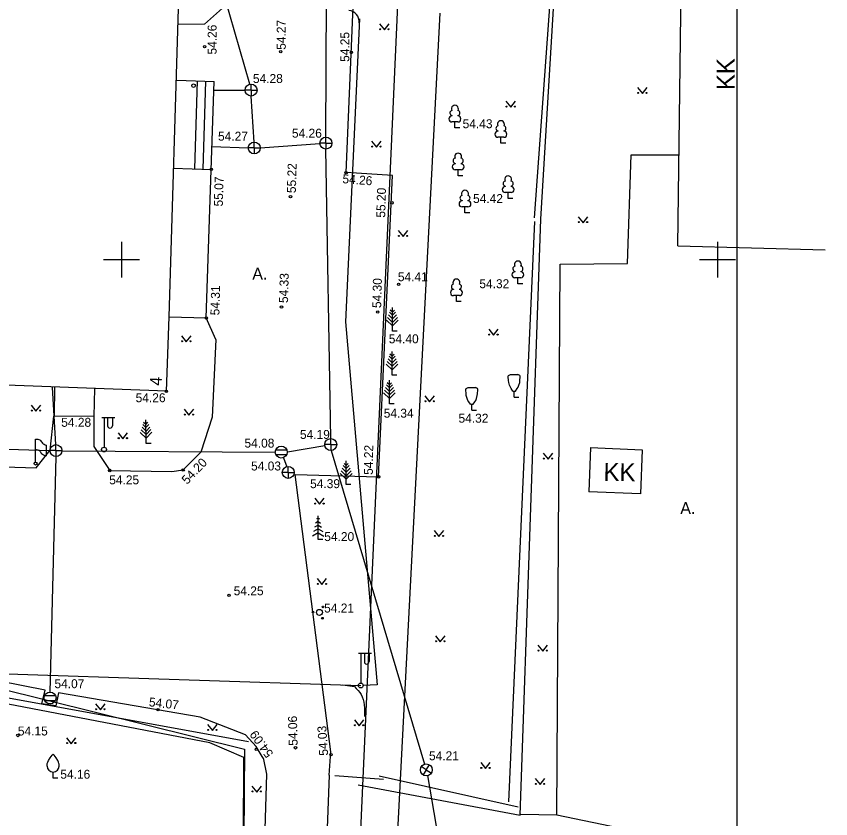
# Model space of a CAD drawing. Extents: x 9156 to 9809, y 2728 to 4000.
# Drawn here: x 9741.2 to 9809.5, y 3703.1 to 3770.4 of the extents above; entities that cross this region are included whole.
import ezdxf

# ---------------------------------------------------------------- set-up
doc = ezdxf.new("R2010")
doc.units = 0
for name, color, linetype in [('Level 1', 7, 'Continuous'), ('Level 54', 7, 'Continuous'), ('Level 63', 7, 'Continuous')]:
    doc.layers.add(name, color=color, linetype=linetype)

msp = doc.modelspace()

# ---------------------------------------------------------------- linework, layer by layer
at = {"layer": 'Level 1'}
for p, q in [((9518.632, 3768.823), (9760.318, 3708.94)), ((9518.632, 3768.823), (9760.318, 3708.94)), ((9760.318, 3708.94), (9759.918, 3646.584)), ((9760.318, 3708.94), (9759.918, 3646.584))]:
    msp.add_line(p, q, dxfattribs=at)
at = {"layer": 'Level 54'}
for p, q in [((9785.171, 3753.397), (9789.782, 3829.186)), ((9774.628, 3803.86), (9769.636, 3693.047)), ((9784.66, 3753.508), (9788.046, 3800.39)), ((9753.989, 3745.191), (9755.299, 3788.499)), ((9767.154, 3760.265), (9767.24, 3788.334)), ((9760.753, 3764.715), (9757.639, 3775.604)), ((9772.838, 3695.211), (9776.735, 3770.688)), ((9756.967, 3769.743), (9754.736, 3769.733)), ((9769.959, 3770.201), (9768.796, 3744.791)), ((9771.656, 3769.774), (9772.059, 3769.269)), ((9772.059, 3769.269), (9772.456, 3769.774)), ((9754.631, 3765.053), (9757.774, 3764.948)), ((9756.164, 3757.619), (9756.387, 3764.995)), ((9756.857, 3757.595), (9757.08, 3764.972)), ((9760.371, 3764.183), (9757.748, 3764.199)), ((9760.868, 3764.22), (9760.368, 3764.22)), ((9760.868, 3764.22), (9760.868, 3764.72)), ((9760.868, 3764.22), (9761.368, 3764.22)), ((9760.868, 3764.22), (9760.868, 3763.72)), ((9793.302, 3764.435), (9793.705, 3763.93)), ((9793.705, 3763.93), (9794.102, 3764.435)), ((9761.13, 3759.861), (9760.88, 3763.715)), ((9782.256, 3763.287), (9782.659, 3762.781)), ((9782.659, 3762.781), (9783.056, 3763.287)), ((9777.721, 3762.085), (9777.721, 3762.053)), ((9778.221, 3761.553), (9777.721, 3761.553)), ((9777.971, 3761.053), (9777.971, 3761.553)), ((9778.221, 3762.085), (9778.221, 3762.053)), ((9778.371, 3761.053), (9777.971, 3761.053)), ((9781.581, 3760.794), (9781.581, 3760.762)), ((9782.081, 3760.794), (9782.081, 3760.762)), ((9767.15, 3759.771), (9767.15, 3760.271)), ((9782.081, 3760.262), (9781.581, 3760.262)), ((9781.831, 3759.762), (9781.831, 3760.262)), ((9760.636, 3759.354), (9757.59, 3759.459)), ((9761.139, 3759.365), (9761.139, 3759.865)), ((9761.646, 3759.366), (9766.639, 3759.749)), ((9767.15, 3759.771), (9766.65, 3759.771)), ((9767.15, 3759.771), (9767.65, 3759.771)), ((9767.15, 3759.771), (9767.15, 3759.271)), ((9770.986, 3759.931), (9771.389, 3759.426)), ((9771.389, 3759.426), (9771.786, 3759.931)), ((9782.231, 3759.762), (9781.831, 3759.762)), ((9761.139, 3759.365), (9760.639, 3759.365)), ((9761.139, 3759.365), (9761.639, 3759.365)), ((9761.139, 3759.365), (9761.139, 3758.865)), ((9767.568, 3734.982), (9767.144, 3759.264)), ((9777.992, 3758.07), (9777.992, 3758.038)), ((9778.492, 3758.07), (9778.492, 3758.038)), ((9754.34, 3757.68), (9757.527, 3757.573)), ((9778.492, 3757.538), (9777.992, 3757.538)), ((9778.242, 3757.038), (9778.242, 3757.538)), ((9778.642, 3757.038), (9778.242, 3757.038)), ((9782.187, 3756.158), (9782.187, 3756.126)), ((9782.687, 3756.158), (9782.687, 3756.126)), ((9782.687, 3755.626), (9782.187, 3755.626)), ((9782.437, 3755.126), (9782.437, 3755.626)), ((9778.566, 3754.955), (9778.566, 3754.923)), ((9779.066, 3754.955), (9779.066, 3754.923)), ((9782.837, 3755.126), (9782.437, 3755.126)), ((9779.066, 3754.423), (9778.566, 3754.423)), ((9778.816, 3753.923), (9778.816, 3754.423)), ((9779.216, 3753.923), (9778.816, 3753.923)), ((9783.44, 3703.4), (9785.171, 3753.397)), ((9788.314, 3753.603), (9788.717, 3753.098)), ((9788.717, 3753.098), (9789.114, 3753.603)), ((9784.647, 3753.209), (9782.461, 3704.513)), ((9773.218, 3752.437), (9773.621, 3751.932)), ((9773.621, 3751.932), (9774.018, 3752.437)), ((9750, 3751.5), (9750, 3748.5)), ((9800, 3751.5), (9800, 3748.5)), ((9796.678, 3751.167), (9809.033, 3750.808)), ((9748.5, 3750), (9751.5, 3750)), ((9798.5, 3750), (9801.5, 3750)), ((9783.006, 3749.013), (9783.006, 3748.981)), ((9783.506, 3748.481), (9783.006, 3748.481)), ((9783.256, 3747.981), (9783.256, 3748.481)), ((9783.506, 3749.013), (9783.506, 3748.981)), ((9783.656, 3747.981), (9783.256, 3747.981)), ((9777.847, 3747.515), (9777.847, 3747.482)), ((9778.347, 3747.515), (9778.347, 3747.482)), ((9778.347, 3746.982), (9777.847, 3746.982)), ((9778.097, 3746.482), (9778.097, 3746.982)), ((9778.497, 3746.482), (9778.097, 3746.482)), ((9772.731, 3745.588), (9772.55, 3745.769)), ((9772.731, 3743.988), (9772.731, 3745.988)), ((9772.731, 3745.588), (9772.912, 3745.769)), ((9757.913, 3743.3), (9757.11, 3745.104)), ((9772.731, 3744.738), (9772.32, 3745.149)), ((9772.731, 3745.038), (9772.401, 3745.368)), ((9772.731, 3745.338), (9772.482, 3745.587)), ((9772.731, 3745.338), (9772.98, 3745.587)), ((9772.731, 3745.038), (9773.061, 3745.368)), ((9772.731, 3744.738), (9773.142, 3745.149)), ((9768.796, 3744.791), (9771.443, 3714.328)), ((9772.731, 3744.438), (9772.239, 3744.93)), ((9772.731, 3744.438), (9773.223, 3744.93)), ((9773.131, 3743.988), (9772.731, 3743.988)), ((9780.805, 3744.16), (9781.208, 3743.654)), ((9781.208, 3743.654), (9781.605, 3744.16)), ((9755.031, 3743.6), (9755.434, 3743.095)), ((9755.434, 3743.095), (9755.831, 3743.6)), ((9772.703, 3740.3), (9772.703, 3742.3)), ((9772.703, 3741.35), (9772.373, 3741.68)), ((9772.703, 3741.65), (9772.454, 3741.899)), ((9772.703, 3741.9), (9772.522, 3742.081)), ((9772.703, 3741.9), (9772.884, 3742.081)), ((9772.703, 3741.65), (9772.951, 3741.899)), ((9772.703, 3741.35), (9773.032, 3741.68)), ((9772.703, 3740.75), (9772.211, 3741.242)), ((9772.703, 3741.05), (9772.292, 3741.461)), ((9772.703, 3741.05), (9773.113, 3741.461)), ((9772.703, 3740.75), (9773.195, 3741.242)), ((9773.103, 3740.3), (9772.703, 3740.3)), ((9782.644, 3740.369), (9783.244, 3740.369)), ((9753.767, 3738.957), (9723.208, 3740.129)), ((9772.478, 3739.494), (9772.297, 3739.675)), ((9772.478, 3737.894), (9772.478, 3739.894)), ((9772.478, 3739.494), (9772.659, 3739.675)), ((9744.503, 3734.483), (9744.199, 3739.278)), ((9744.39, 3739.317), (9744.351, 3736.881)), ((9747.729, 3739.189), (9747.691, 3736.827)), ((9772.478, 3738.644), (9772.067, 3739.054)), ((9772.478, 3738.944), (9772.148, 3739.273)), ((9772.478, 3739.244), (9772.229, 3739.492)), ((9772.478, 3739.244), (9772.726, 3739.492)), ((9772.478, 3738.944), (9772.807, 3739.273)), ((9772.478, 3738.644), (9772.889, 3739.054)), ((9779.09, 3739.263), (9779.69, 3739.263)), ((9782.844, 3738.969), (9783.044, 3738.969)), ((9782.944, 3738.469), (9782.944, 3738.969)), ((9772.478, 3738.344), (9771.986, 3738.836)), ((9772.478, 3738.344), (9772.97, 3738.836)), ((9775.449, 3738.567), (9775.852, 3738.062)), ((9775.852, 3738.062), (9776.249, 3738.567)), ((9782.944, 3738.469), (9783.344, 3738.469)), ((9742.422, 3737.784), (9742.825, 3737.279)), ((9742.825, 3737.279), (9743.222, 3737.784)), ((9772.878, 3737.894), (9772.478, 3737.894)), ((9779.29, 3737.863), (9779.49, 3737.863)), ((9779.39, 3737.363), (9779.39, 3737.863)), ((9747.691, 3736.827), (9744.351, 3736.881)), ((9747.691, 3736.827), (9747.691, 3736.827)), ((9755.254, 3737.448), (9755.657, 3736.943)), ((9755.657, 3736.943), (9756.054, 3737.448)), ((9779.39, 3737.363), (9779.79, 3737.363)), ((9748.335, 3736.764), (9749.435, 3736.763)), ((9748.535, 3736.764), (9748.531, 3734.264)), ((9748.835, 3736.763), (9748.834, 3736.063)), ((9749.235, 3736.763), (9749.234, 3736.063)), ((9752.049, 3735.916), (9751.795, 3736.159)), ((9752.043, 3736.166), (9751.858, 3736.343)), ((9752.08, 3734.567), (9752.034, 3736.566)), ((9752.043, 3736.166), (9752.22, 3736.352)), ((9752.049, 3735.916), (9752.292, 3736.171)), ((9749.712, 3735.472), (9750.115, 3734.967)), ((9750.115, 3734.967), (9750.512, 3735.472)), ((9752.07, 3735.017), (9751.567, 3735.497)), ((9752.063, 3735.317), (9751.643, 3735.718)), ((9752.056, 3735.616), (9751.719, 3735.939)), ((9752.056, 3735.616), (9752.378, 3735.954)), ((9752.063, 3735.317), (9752.464, 3735.737)), ((9752.07, 3735.017), (9752.55, 3735.52)), ((9742.786, 3733.015), (9742.786, 3734.941)), ((9742.786, 3733.015), (9742.786, 3734.941)), ((9767.556, 3734.489), (9767.556, 3734.989)), ((9719.974, 3734.745), (9743.999, 3733.987)), ((9743.687, 3734.437), (9743.687, 3733.547)), ((9743.687, 3734.437), (9743.687, 3733.547)), ((9744.503, 3733.983), (9744.503, 3734.483)), ((9752.48, 3734.576), (9752.08, 3734.567)), ((9763.914, 3733.865), (9767.061, 3734.403)), ((9767.556, 3734.489), (9767.056, 3734.489)), ((9767.556, 3734.489), (9768.056, 3734.489)), ((9767.556, 3734.489), (9767.556, 3733.989)), ((9789.34, 3734.253), (9789.195, 3730.514)), ((9789.34, 3734.253), (9793.692, 3734.034)), ((9744.503, 3733.983), (9744.003, 3733.983)), ((9744.006, 3713.727), (9744.507, 3733.462)), ((9744.503, 3733.983), (9745.003, 3733.983)), ((9744.503, 3733.983), (9744.503, 3733.483)), ((9745.004, 3733.97), (9762.922, 3733.856)), ((9762.944, 3734.055), (9763.86, 3734.055)), ((9762.944, 3733.655), (9763.86, 3733.655)), ((9767.576, 3733.979), (9775.425, 3707.676)), ((9785.38, 3733.757), (9785.783, 3733.252)), ((9785.783, 3733.252), (9786.18, 3733.757)), ((9793.692, 3734.034), (9793.55, 3730.346)), ((9763.583, 3733.384), (9763.857, 3732.621)), ((9768.848, 3732.472), (9768.6, 3732.72)), ((9768.848, 3732.722), (9768.667, 3732.903)), ((9768.848, 3731.122), (9768.848, 3733.122)), ((9768.848, 3732.722), (9769.029, 3732.903)), ((9768.848, 3732.472), (9769.097, 3732.72)), ((9763.99, 3732.147), (9763.49, 3732.147)), ((9763.99, 3732.147), (9763.99, 3732.647)), ((9763.99, 3732.147), (9764.49, 3732.147)), ((9763.99, 3732.147), (9763.99, 3731.647)), ((9768.848, 3731.572), (9768.356, 3732.064)), ((9768.848, 3731.872), (9768.437, 3732.282)), ((9768.848, 3732.172), (9768.518, 3732.501)), ((9768.848, 3732.172), (9769.178, 3732.501)), ((9768.848, 3731.872), (9769.259, 3732.282)), ((9768.848, 3731.572), (9769.34, 3732.064)), ((9769.248, 3731.122), (9768.848, 3731.122)), ((9766.208, 3729.988), (9766.611, 3729.482)), ((9766.611, 3729.482), (9767.008, 3729.988)), ((9793.55, 3730.346), (9789.195, 3730.514)), ((9766.493, 3728.018), (9766.281, 3727.901)), ((9766.493, 3728.318), (9766.367, 3728.248)), ((9766.493, 3726.518), (9766.493, 3728.518)), ((9766.493, 3728.318), (9766.619, 3728.248)), ((9766.493, 3728.018), (9766.705, 3727.901)), ((9766.493, 3727.418), (9766.109, 3727.205)), ((9766.493, 3727.718), (9766.195, 3727.553)), ((9766.493, 3727.718), (9766.791, 3727.553)), ((9766.493, 3727.418), (9766.877, 3727.205)), ((9776.23, 3727.27), (9776.633, 3726.765)), ((9776.633, 3726.765), (9777.03, 3727.27)), ((9766.493, 3727.068), (9766.018, 3726.804)), ((9766.493, 3727.068), (9766.968, 3726.804)), ((9766.893, 3726.518), (9766.493, 3726.518)), ((9766.411, 3723.243), (9766.814, 3722.738)), ((9766.814, 3722.738), (9767.211, 3723.243)), ((9776.342, 3718.433), (9776.745, 3717.928)), ((9776.745, 3717.928), (9777.142, 3718.433)), ((9760.645, 3709.542), (9715.664, 3717.757)), ((9784.933, 3717.65), (9785.336, 3717.145)), ((9785.336, 3717.145), (9785.733, 3717.65)), ((9769.872, 3716.974), (9770.972, 3716.974)), ((9770.072, 3716.974), (9770.072, 3714.474)), ((9770.372, 3716.974), (9770.372, 3716.274)), ((9770.772, 3716.974), (9770.772, 3716.274)), ((9739.367, 3715.288), (9770.072, 3714.274)), ((9768.565, 3714.327), (9769.542, 3714.187)), ((9771.443, 3714.328), (9770.272, 3714.274)), ((9743.548, 3713.427), (9744.464, 3713.427)), ((9743.548, 3713.027), (9744.464, 3713.027)), ((9747.822, 3712.732), (9748.225, 3712.227)), ((9748.225, 3712.227), (9748.622, 3712.732)), ((9757.227, 3711.001), (9757.63, 3710.496)), ((9757.63, 3710.496), (9758.027, 3711.001)), ((9769.536, 3711.387), (9769.939, 3710.881)), ((9769.939, 3710.881), (9770.336, 3711.387)), ((9745.379, 3709.896), (9745.779, 3709.392)), ((9745.779, 3709.392), (9746.179, 3709.896)), ((9775.572, 3707.198), (9775.15, 3707.468)), ((9775.572, 3707.198), (9775.841, 3707.62)), ((9780.136, 3707.807), (9780.539, 3707.302)), ((9780.539, 3707.302), (9780.936, 3707.807)), ((9744.263, 3706.511), (9744.263, 3707.011)), ((9775.572, 3707.198), (9775.302, 3706.777)), ((9775.572, 3707.198), (9775.993, 3706.929)), ((9744.663, 3706.511), (9744.263, 3706.511)), ((9767.89, 3706.722), (9771.986, 3706.426)), ((9767.89, 3706.722), (9771.986, 3706.426)), ((9771.603, 3706.698), (9783.265, 3704.082)), ((9776.694, 3701.023), (9775.686, 3706.71)), ((9784.71, 3706.465), (9785.113, 3705.96)), ((9785.113, 3705.96), (9785.51, 3706.465)), ((9760.942, 3705.84), (9761.345, 3705.334)), ((9761.345, 3705.334), (9761.742, 3705.84)), ((9769.867, 3705.934), (9783.44, 3703.4)), ((9786.533, 3703.398), (9783.497, 3703.443))]:
    msp.add_line(p, q, dxfattribs=at)
for points in [[(9767.422, 3706.742), (9767.572, 3708.712), (9764.558, 3731.978), (9771.571, 3731.778), (9772.74, 3757.064), (9768.845, 3757.295), (9770.211, 3789.798)], [(9796.678, 3751.167), (9797.064, 3781.422), (9809.499, 3781.315)], [(9756.967, 3769.743), (9758.721, 3771.315), (9758.954, 3775.466), (9757.975, 3776.546)], [(9756.967, 3769.743), (9758.721, 3771.315), (9758.954, 3775.466), (9757.975, 3776.546)], [(9753.767, 3738.957), (9753.989, 3745.191), (9757.11, 3745.104), (9757.774, 3764.948)], [(9786.812, 3749.615), (9792.455, 3749.663), (9792.753, 3758.79), (9796.776, 3758.79)], [(9767.422, 3706.742), (9766.108, 3671.895), (9767.144, 3668.733), (9769.945, 3667.658), (9773.297, 3669.035), (9776.656, 3671.629), (9777.695, 3673.366), (9778.596, 3677.747), (9783.22, 3677.134), (9786.444, 3677.921), (9788.772, 3679.249), (9790.545, 3682.009), (9791.784, 3702.308), (9786.533, 3703.398), (9786.812, 3749.615)], [(9757.913, 3743.3), (9757.609, 3736.775), (9756.642, 3733.853), (9755.169, 3732.357), (9755.169, 3732.357)], [(9782.844, 3738.969), (9782.686, 3739.182), (9782.621, 3739.294), (9782.544, 3739.469), (9782.483, 3739.695), (9782.459, 3739.851), (9782.444, 3740.169), (9782.446, 3740.211), (9782.476, 3740.282), (9782.516, 3740.32), (9782.644, 3740.369)], [(9783.044, 3738.969), (9783.203, 3739.182), (9783.267, 3739.294), (9783.344, 3739.469), (9783.405, 3739.695), (9783.429, 3739.851), (9783.444, 3740.169), (9783.442, 3740.211), (9783.412, 3740.282), (9783.372, 3740.319), (9783.244, 3740.369)], [(9779.29, 3737.863), (9779.132, 3738.076), (9779.067, 3738.188), (9778.99, 3738.363), (9778.929, 3738.588), (9778.905, 3738.744), (9778.89, 3739.063), (9778.892, 3739.105), (9778.922, 3739.176), (9778.962, 3739.213), (9779.09, 3739.263)], [(9779.49, 3737.863), (9779.648, 3738.076), (9779.713, 3738.188), (9779.79, 3738.363), (9779.851, 3738.588), (9779.875, 3738.744), (9779.89, 3739.063), (9779.888, 3739.105), (9779.858, 3739.176), (9779.818, 3739.213), (9779.69, 3739.263)], [(9724.886, 3733.079), (9742.842, 3732.535), (9744.003, 3734.005), (9744.316, 3736.875)], [(9747.691, 3736.813), (9747.678, 3734.333), (9749.007, 3732.308), (9754.211, 3732.232), (9755.169, 3732.357)], [(9762.185, 3706.838), (9761.899, 3708.198), (9761.872, 3708.168), (9761.309, 3709.17), (9760.395, 3710.143), (9756.61, 3711.63), (9744.711, 3713.671), (9744.494, 3712.557), (9743.325, 3712.733), (9743.586, 3713.889), (9716.595, 3719.196), (9717.559, 3733.926)], [(9669.366, 3700.509), (9706.561, 3695.721), (9760.177, 3687.877), (9760.263, 3708.241), (9757.403, 3709.459), (9722.811, 3716.105)], [(9743.763, 3707.511), (9743.763, 3707.661), (9743.773, 3707.727), (9743.81, 3707.855), (9743.866, 3707.979), (9744.013, 3708.211), (9744.173, 3708.416), (9744.263, 3708.511)], [(9744.763, 3707.511), (9744.763, 3707.661), (9744.753, 3707.727), (9744.715, 3707.855), (9744.659, 3707.979), (9744.513, 3708.211), (9744.353, 3708.416), (9744.263, 3708.511)], [(9668.849, 3683.691), (9716.728, 3673.571), (9733.181, 3670.306), (9749.81, 3667.577), (9753.185, 3667.02), (9755.937, 3666.713), (9759.285, 3666.165), (9760.87, 3667.83), (9761.204, 3674.559), (9762.185, 3706.838)]]:
    msp.add_lwpolyline(points, dxfattribs=at)
for centre, radius in [((9771.706, 3769.324), 0.0428), ((9772.406, 3769.324), 0.0452), ((9756.971, 3767.874), 0.102), ((9763.36, 3767.438), 0.102), ((9769.286, 3767.393), 0.102), ((9756.045, 3764.596), 0.152), ((9760.868, 3764.22), 0.5), ((9793.352, 3763.985), 0.0428), ((9794.052, 3763.985), 0.0452), ((9782.306, 3762.837), 0.0428), ((9783.006, 3762.837), 0.0452), ((9767.15, 3759.771), 0.5), ((9761.139, 3759.365), 0.5), ((9771.036, 3759.481), 0.0428), ((9771.736, 3759.481), 0.0452), ((9757.527, 3757.573), 0.102), ((9768.845, 3757.295), 0.102), ((9764.177, 3755.275), 0.102), ((9772.681, 3754.762), 0.102), ((9788.364, 3753.153), 0.0428), ((9789.064, 3753.153), 0.0452), ((9773.268, 3751.987), 0.0428), ((9773.968, 3751.987), 0.0452), ((9773.249, 3747.933), 0.102), ((9763.42, 3746.02), 0.102), ((9771.498, 3745.605), 0.102), ((9757.11, 3745.104), 0.102), ((9780.855, 3743.71), 0.0428), ((9781.555, 3743.71), 0.0452), ((9755.081, 3743.15), 0.0428), ((9755.781, 3743.15), 0.0452), ((9753.767, 3738.957), 0.102), ((9775.499, 3738.117), 0.0428), ((9776.199, 3738.117), 0.0452), ((9742.472, 3737.334), 0.0428), ((9743.172, 3737.334), 0.0452), ((9755.304, 3736.998), 0.0428), ((9756.004, 3736.998), 0.0452), ((9749.762, 3735.022), 0.0428), ((9750.462, 3735.022), 0.0452), ((9767.556, 3734.489), 0.5), ((9744.503, 3733.983), 0.5), ((9748.531, 3734.064), 0.2), ((9763.402, 3733.855), 0.5), ((9742.786, 3732.889), 0.126), ((9742.786, 3732.889), 0.126), ((9785.43, 3733.307), 0.0428), ((9786.13, 3733.307), 0.0452), ((9749.007, 3732.308), 0.102), ((9755.169, 3732.357), 0.102), ((9763.99, 3732.147), 0.5), ((9771.571, 3731.778), 0.102), ((9766.258, 3729.538), 0.0428), ((9766.958, 3729.538), 0.0452), ((9776.28, 3726.82), 0.0428), ((9776.98, 3726.82), 0.0452), ((9766.461, 3722.793), 0.0428), ((9767.161, 3722.793), 0.0452), ((9759.025, 3721.829), 0.102), ((9766.059, 3720.433), 0.0707), ((9766.608, 3720.408), 0.25), ((9766.904, 3720.871), 0.0707), ((9766.861, 3719.92), 0.0707), ((9776.392, 3717.983), 0.0428), ((9777.092, 3717.983), 0.0452), ((9784.983, 3717.2), 0.0428), ((9785.683, 3717.2), 0.0452), ((9770.072, 3714.274), 0.2), ((9744.006, 3713.227), 0.5), ((9747.872, 3712.282), 0.0428), ((9748.572, 3712.282), 0.0452), ((9753.066, 3712.252), 0.102), ((9769.586, 3710.937), 0.0428), ((9770.286, 3710.937), 0.0452), ((9741.304, 3710.083), 0.102), ((9757.277, 3710.551), 0.0428), ((9757.977, 3710.551), 0.0452), ((9746.129, 3709.446), 0.0486), ((9745.429, 3709.446), 0.0407), ((9761.309, 3708.92), 0.102), ((9764.598, 3709.047), 0.102), ((9767.572, 3708.462), 0.102), ((9775.572, 3707.198), 0.5), ((9780.186, 3707.357), 0.0428), ((9780.886, 3707.357), 0.0452), ((9760.992, 3705.39), 0.0428), ((9761.692, 3705.39), 0.0452), ((9784.76, 3706.015), 0.0428), ((9785.46, 3706.015), 0.0452)]:
    msp.add_circle(centre, radius, dxfattribs=at)
for centre, radius, start, end in [((9768.945, 3769.918), 1, 357.38123, 82.62243), ((9777.971, 3762.653), 0.292, 332.57912, 207.41932), ((9777.771, 3762.303), 0.224, 105.24332, 257.07825), ((9778.171, 3762.303), 0.224, 282.92018, 74.75512), ((9777.721, 3761.803), 0.25, 89.99922, 269.99922), ((9778.221, 3761.803), 0.25, 269.99922, 89.99921), ((9781.831, 3761.362), 0.292, 332.57912, 207.41932), ((9781.581, 3760.512), 0.25, 89.99922, 269.99922), ((9781.631, 3761.012), 0.224, 105.24332, 257.07825), ((9782.031, 3761.012), 0.224, 282.92018, 74.75512), ((9782.081, 3760.512), 0.25, 269.99922, 89.99921), ((9778.242, 3758.638), 0.292, 332.57912, 207.41932), ((9777.992, 3757.788), 0.25, 89.99922, 269.99922), ((9778.042, 3758.288), 0.224, 105.24332, 257.07825), ((9778.442, 3758.288), 0.224, 282.92018, 74.75512), ((9778.492, 3757.788), 0.25, 269.99922, 89.99921), ((9782.437, 3756.726), 0.292, 332.57912, 207.41932), ((9782.187, 3755.876), 0.25, 89.99922, 269.99922), ((9782.237, 3756.376), 0.224, 105.24332, 257.07825), ((9782.637, 3756.376), 0.224, 282.92018, 74.75512), ((9782.687, 3755.876), 0.25, 269.99922, 89.99921), ((9778.616, 3755.173), 0.224, 105.24332, 257.07825), ((9778.816, 3755.523), 0.292, 332.57912, 207.41932), ((9779.016, 3755.173), 0.224, 282.92018, 74.75512), ((9778.566, 3754.673), 0.25, 89.99922, 269.99922), ((9779.066, 3754.673), 0.25, 269.99922, 89.99921), ((9783.256, 3749.581), 0.292, 332.57912, 207.41932), ((9783.056, 3749.231), 0.224, 105.24332, 257.07825), ((9783.456, 3749.231), 0.224, 282.92018, 74.75512), ((9783.006, 3748.731), 0.25, 89.99922, 269.99922), ((9783.506, 3748.731), 0.25, 269.99922, 89.99921), ((9777.897, 3747.732), 0.224, 105.24332, 257.07825), ((9778.097, 3748.082), 0.292, 332.57912, 207.41932), ((9778.297, 3747.732), 0.224, 282.92018, 74.75512), ((9777.847, 3747.232), 0.25, 89.99922, 269.99922), ((9778.347, 3747.232), 0.25, 269.99922, 89.99921), ((9749.034, 3736.063), 0.2, 179.86432, 359.98571), ((9770.572, 3716.273), 0.2, 179.93931, 0.0607), ((9744.263, 3707.511), 0.5, 180, 0)]:
    msp.add_arc(centre, radius, start, end, dxfattribs=at)
for points in [[(9742.786, 3734.941), (9743.136, 3734.876), (9743.368, 3734.61), (9743.687, 3734.437)], [(9742.786, 3734.941), (9743.136, 3734.876), (9743.368, 3734.61), (9743.687, 3734.437)], [(9742.786, 3734.066), (9743.113, 3733.977), (9743.28, 3733.744), (9743.688, 3733.548)], [(9742.786, 3734.066), (9743.113, 3733.977), (9743.28, 3733.744), (9743.688, 3733.548)], [(9769.542, 3714.187), (9770.098, 3713.518), (9770.399, 3711.66)]]:
    msp.add_spline(points, degree=3, dxfattribs=at)
at = {"layer": 'Level 63'}
msp.add_lwpolyline([(9275.527, 3966.797), (9801.617, 3966.797), (9801.617, 3329.636), (9275.527, 3329.636)], close=True, dxfattribs=at)

# ---------------------------------------------------------------- texts
at = {"layer": 'Level 54'}
for s, height, rotation, p in [('54.26', 0.75, 90, (9757.975, 3767.203)), ('54.27', 0.75, 90, (9763.778, 3767.6)), ('54.25', 0.75, 90, (9769.113, 3766.588)), ('KK', 1.5, 90, (9801.439, 3764.219)), ('55.22', 0.75, 88.3129, (9764.62, 3755.57)), ('55.07', 0.75, 88.3129, (9758.493, 3754.45)), ('54.26', 0.75, 355.75131, (9768.514, 3756.415)), ('55.20', 0.75, 88.3129, (9772.118, 3753.511)), ('54.33', 0.75, 88.4762, (9763.965, 3746.35)), ('54.31', 0.75, 88.4762, (9758.208, 3745.318)), ('54.30', 0.75, 88.4762, (9771.782, 3745.928)), ('4', 1, 88.09558, (9753.365, 3739.411)), ('54.28', 0.75, 0.03691, (9744.941, 3735.976)), ('54.22', 0.75, 89.19487, (9771.083, 3731.94)), ('54.20', 0.75, 46.06126, (9755.503, 3731.1)), ('KK', 1.5, 359.25776, (9790.43, 3731.445)), ('54.07', 0.75, 353.61697, (9752.268, 3712.537)), ('54.06', 0.75, 91.32997, (9764.775, 3709.229)), ('54.03', 0.75, 93.90105, (9767.342, 3708.41)), ('54.09', 0.75, 125.68263, (9762.775, 3708.555))]:
    msp.add_text(s, height=height, rotation=rotation, dxfattribs=at).set_placement(p)
for s, height, p in [('54.28', 0.75, (9761.024, 3764.816)), ('54.43', 0.75, (9778.616, 3761.025)), ('54.27', 0.75, (9758.097, 3759.979)), ('54.26', 0.75, (9764.297, 3760.232)), ('54.42', 0.75, (9779.493, 3754.749)), ('A.', 1, (9760.975, 3748.321)), ('54.41', 0.75, (9773.186, 3748.19)), ('54.32', 0.75, (9780.022, 3747.603)), ('54.40', 0.75, (9772.421, 3742.983)), ('54.26', 0.75, (9751.184, 3738.04)), ('54.34', 0.75, (9771.999, 3736.741)), ('54.32', 0.75, (9778.273, 3736.321)), ('54.19', 0.75, (9764.969, 3734.96)), ('54.08', 0.75, (9760.315, 3734.232)), ('54.03', 0.75, (9760.87, 3732.313)), ('54.25', 0.75, (9748.969, 3731.152)), ('54.39', 0.75, (9765.822, 3730.829)), ('A.', 1, (9796.882, 3728.661)), ('54.20', 0.75, (9767.01, 3726.39)), ('54.25', 0.75, (9759.409, 3721.841)), ('54.21', 0.75, (9766.999, 3720.397)), ('54.07', 0.75, (9744.373, 3714.049)), ('54.15', 0.75, (9741.304, 3710.083)), ('54.21', 0.75, (9775.796, 3708.005)), ('54.16', 0.75, (9744.866, 3706.455))]:
    msp.add_text(s, height=height, dxfattribs=at).set_placement(p)

doc.saveas('drawing.dxf')
